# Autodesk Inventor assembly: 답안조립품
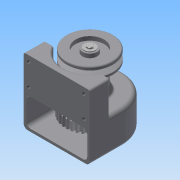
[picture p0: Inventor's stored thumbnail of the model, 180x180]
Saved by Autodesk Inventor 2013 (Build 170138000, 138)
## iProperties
Created: 2011-02
Part Number: 답안조립품
Document SubType Name: Assembly
Designer: Administrator
Author: Administrator
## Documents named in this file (14)
- C:\Documents and Settings\Administrator\바탕 화면\450214V1026\답안조립품.iam
- C:\Documents and Settings\Administrator\바탕 화면\450214V1026\1-본체.ipt
- C:\Documents and Settings\Administrator\바탕 화면\450214V1026\베어링 6001.ipt
- C:\Documents and Settings\Administrator\바탕 화면\450214V1026\축.ipt
- C:\Documents and Settings\Administrator\바탕 화면\450214V1026\키5x5.ipt
- C:\Documents and Settings\Administrator\바탕 화면\450214V1026\5-스퍼기어.ipt
- C:\Documents and Settings\Administrator\바탕 화면\450214V1026\키4x4.ipt
- C:\Documents and Settings\Administrator\바탕 화면\450214V1026\축커버.ipt
- C:\Documents and Settings\Administrator\바탕 화면\450214V1026\4-벨트풀리.ipt
- C:\Documents and Settings\Administrator\바탕 화면\450214V1026\오일실.ipt
- C:\Documents and Settings\Administrator\바탕 화면\450214V1026\M3x0.5.ipt
- C:\Documents and Settings\Administrator\바탕 화면\450214V1026\와샤.ipt
- C:\Documents and Settings\Administrator\바탕 화면\450214V1026\M5x0.8.ipt
- M5x0.8.ipt
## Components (7 placed, 4 different names)
1. 1-본체:1
2. 4-벨트풀리:1 — 각도:4
3. M5x0.8:1 — 각도:5
4. M3x0.5:1
5. M3x0.5:2
6. M3x0.5:3
7. M3x0.5:4
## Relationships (2: Angle 2)
- 각도:4 [Angle]: 4-벨트풀리:1
- 각도:5 [Angle]: M5x0.8:1
